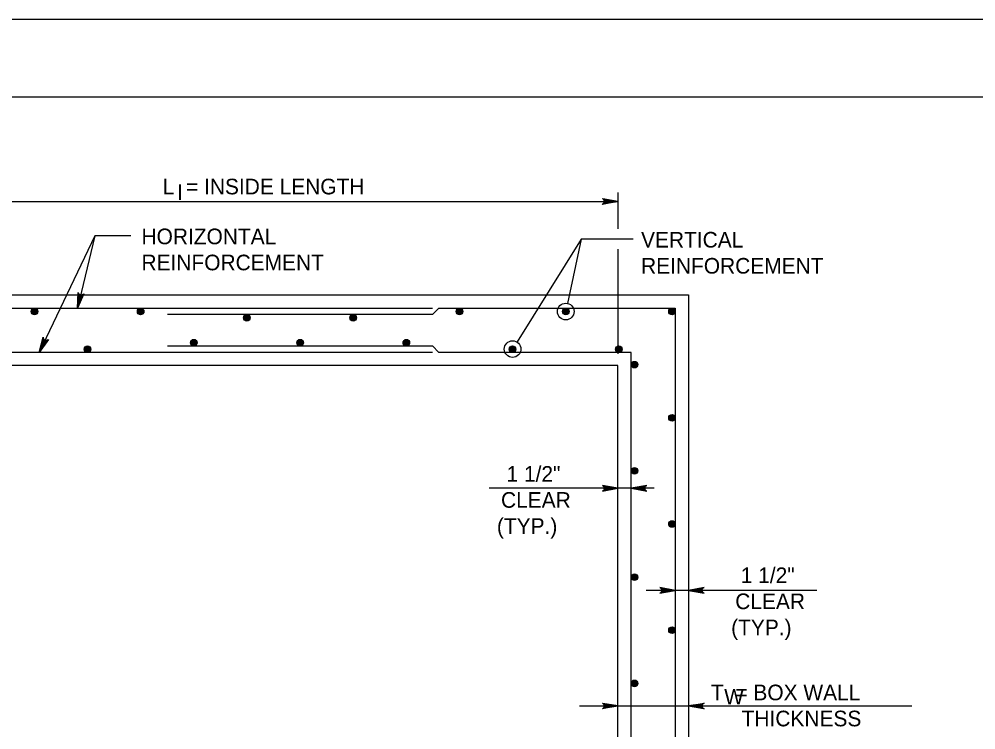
# Model space of a CAD drawing. Extents: x -6420 to 49575, y -4552 to 11624.
# Drawn here: x 3139 to 3741, y 3381 to 3829 of the extents above; entities that cross this region are included whole.
import ezdxf

# ---------------------------------------------------------------- set-up
doc = ezdxf.new("R2010")
doc.units = 0
doc.layers.add('1', color=7, linetype='Continuous')
doc.layers.add('PLT-BNDY', color=7, linetype='Continuous')

msp = doc.modelspace()

# ---------------------------------------------------------------- linework, layer by layer
at = {"layer": '1'}
for p, q in [((3516, 3719.59), (3516, 3696.6)), ((3115.99, 3713.89), (3516, 3713.89)), ((3186.81, 3692.29), (3151.76, 3618.89)), ((3186.81, 3692.29), (3175.85, 3646.67)), ((3209.46, 3692.29), (3186.81, 3692.29)), ((3492.81, 3690.2), (3452.5, 3625.43)), ((3492.81, 3690.2), (3484.25, 3649.72)), ((3525.48, 3690.2), (3492.81, 3690.2)), ((3516, 3683.79), (3516, 3617.96)), ((3079.87, 3646.67), (3399.33, 3646.67)), ((3399.33, 3642.67), (3232.66, 3642.67)), ((3399.33, 3642.67), (3403.33, 3646.67)), ((3403.33, 3646.67), (3552.11, 3646.67)), ((3483.16, 3644.58), (3483.16, 3644.58)), ((3552.11, 3646.67), (3552.11, 3174.43)), ((3399.33, 3618.89), (3107.66, 3618.89)), ((3232.66, 3622.89), (3399.33, 3622.89)), ((3399.33, 3622.89), (3403.33, 3618.89)), ((3524.33, 3618.89), (3403.33, 3618.89)), ((3449.73, 3620.97), (3449.73, 3620.97)), ((3524.33, 3202.21), (3524.33, 3618.89)), ((3538.89, 3533.32), (3434.99, 3533.32)), ((3641.23, 3469.09), (3533.8, 3469.09)), ((3491.9, 3396.36), (3700.86, 3396.36))]:
    msp.add_line(p, q, dxfattribs=at)
for points in [[(4563.89, 1929.01), (4563.89, 3779.41), (1985.15, 3779.41), (1985.15, 1929.01), (4563.89, 1929.01), (4563.89, 2015.49), (3907.72, 2015.49), (3907.72, 2227.69), (4563.89, 2227.69), (4563.89, 2322.72), (3907.72, 2322.72), (3907.72, 1929.01), (4166.25, 1929.01), (4166.25, 2015.49), (4166.25, 1929.01), (4418.88, 1929.01), (4418.88, 2015.49), (4418.88, 1975.09), (4563.89, 1975.09)], [(3516, 3713.89), (3506.21, 3712.05), (3506.59, 3712.31), (3506.97, 3712.58), (3507.16, 3712.9), (3507.35, 3713.23), (3507.41, 3713.56), (3507.47, 3713.89), (3507.41, 3714.22), (3507.35, 3714.54), (3507.16, 3714.87), (3506.97, 3715.2), (3506.59, 3715.46), (3506.21, 3715.72), (3516, 3713.89), (3506.59, 3715.46), (3506.97, 3715.2), (3516, 3713.89), (3507.16, 3714.87), (3507.35, 3714.54), (3516, 3713.89), (3507.41, 3714.22), (3507.47, 3713.89), (3516, 3713.89), (3507.41, 3713.56), (3507.35, 3713.23), (3516, 3713.89), (3507.16, 3712.9), (3506.97, 3712.58), (3516, 3713.89), (3506.59, 3712.31)], [(3175.85, 3646.67), (3176.35, 3656.61), (3176.52, 3656.18), (3176.69, 3655.76), (3176.96, 3655.49), (3177.23, 3655.22), (3177.54, 3655.09), (3177.85, 3654.96), (3178.18, 3654.94), (3178.51, 3654.92), (3178.87, 3655.03), (3179.24, 3655.14), (3179.58, 3655.45), (3179.92, 3655.75), (3175.85, 3646.67), (3179.58, 3655.45), (3179.24, 3655.14), (3175.85, 3646.67), (3178.87, 3655.03), (3178.51, 3654.92), (3175.85, 3646.67), (3178.18, 3654.94), (3177.85, 3654.96), (3175.85, 3646.67), (3177.54, 3655.09), (3177.23, 3655.22), (3175.85, 3646.67), (3176.96, 3655.49), (3176.69, 3655.76), (3175.85, 3646.67), (3176.52, 3656.18)], [(3151.76, 3618.89), (3154.32, 3628.51), (3154.39, 3628.06), (3154.46, 3627.6), (3154.68, 3627.29), (3154.89, 3626.97), (3155.16, 3626.78), (3155.43, 3626.58), (3155.75, 3626.49), (3156.07, 3626.4), (3156.45, 3626.44), (3156.83, 3626.47), (3157.23, 3626.7), (3157.63, 3626.93), (3151.76, 3618.89), (3157.23, 3626.7), (3156.83, 3626.47), (3151.76, 3618.89), (3156.45, 3626.44), (3156.07, 3626.4), (3151.76, 3618.89), (3155.75, 3626.49), (3155.43, 3626.58), (3151.76, 3618.89), (3155.16, 3626.78), (3154.89, 3626.97), (3151.76, 3618.89), (3154.68, 3627.29), (3154.46, 3627.6), (3151.76, 3618.89), (3154.39, 3628.06)], [(3516, 3533.32), (3506.21, 3535.15), (3506.59, 3534.89), (3506.97, 3534.63), (3507.16, 3534.3), (3507.35, 3533.97), (3507.41, 3533.64), (3507.47, 3533.32), (3507.41, 3532.99), (3507.35, 3532.66), (3507.16, 3532.33), (3506.97, 3532), (3506.59, 3531.74), (3506.21, 3531.48), (3516, 3533.32), (3506.59, 3531.74), (3506.97, 3532), (3516, 3533.32), (3507.16, 3532.33), (3507.35, 3532.66), (3516, 3533.32), (3507.41, 3532.99), (3507.47, 3533.32), (3516, 3533.32), (3507.41, 3533.64), (3507.35, 3533.97), (3516, 3533.32), (3507.16, 3534.3), (3506.97, 3534.63), (3516, 3533.32), (3506.59, 3534.89)], [(3524.33, 3533.32), (3534.12, 3531.48), (3533.74, 3531.74), (3533.36, 3532), (3533.17, 3532.33), (3532.97, 3532.66), (3532.92, 3532.99), (3532.86, 3533.32), (3532.92, 3533.64), (3532.97, 3533.97), (3533.17, 3534.3), (3533.36, 3534.63), (3533.74, 3534.89), (3534.12, 3535.15), (3524.33, 3533.32), (3533.74, 3534.89), (3533.36, 3534.63), (3524.33, 3533.32), (3533.17, 3534.3), (3532.97, 3533.97), (3524.33, 3533.32), (3532.92, 3533.64), (3532.86, 3533.32), (3524.33, 3533.32), (3532.92, 3532.99), (3532.97, 3532.66), (3524.33, 3533.32), (3533.17, 3532.33), (3533.36, 3532), (3524.33, 3533.32), (3533.74, 3531.74)], [(3552.11, 3469.09), (3542.33, 3470.92), (3542.7, 3470.66), (3543.08, 3470.4), (3543.27, 3470.07), (3543.47, 3469.74), (3543.52, 3469.42), (3543.58, 3469.09), (3543.52, 3468.76), (3543.47, 3468.43), (3543.27, 3468.1), (3543.08, 3467.78), (3542.7, 3467.51), (3542.33, 3467.25), (3552.11, 3469.09), (3542.7, 3467.51), (3543.08, 3467.78), (3552.11, 3469.09), (3543.27, 3468.1), (3543.47, 3468.43), (3552.11, 3469.09), (3543.52, 3468.76), (3543.58, 3469.09), (3552.11, 3469.09), (3543.52, 3469.42), (3543.47, 3469.74), (3552.11, 3469.09), (3543.27, 3470.07), (3543.08, 3470.4), (3552.11, 3469.09), (3542.7, 3470.66)], [(3560.44, 3469.09), (3570.23, 3467.25), (3569.85, 3467.51), (3569.48, 3467.78), (3569.28, 3468.1), (3569.09, 3468.43), (3569.03, 3468.76), (3568.97, 3469.09), (3569.03, 3469.42), (3569.09, 3469.74), (3569.28, 3470.07), (3569.48, 3470.4), (3569.85, 3470.66), (3570.23, 3470.92), (3560.44, 3469.09), (3569.85, 3470.66), (3569.48, 3470.4), (3560.44, 3469.09), (3569.28, 3470.07), (3569.09, 3469.74), (3560.44, 3469.09), (3569.03, 3469.42), (3568.97, 3469.09), (3560.44, 3469.09), (3569.03, 3468.76), (3569.09, 3468.43), (3560.44, 3469.09), (3569.28, 3468.1), (3569.48, 3467.78), (3560.44, 3469.09), (3569.85, 3467.51)], [(3516, 3396.36), (3506.21, 3394.52), (3506.59, 3394.78), (3506.97, 3395.04), (3507.16, 3395.37), (3507.35, 3395.7), (3507.41, 3396.03), (3507.47, 3396.36), (3507.41, 3396.68), (3507.35, 3397.01), (3507.16, 3397.34), (3506.97, 3397.67), (3506.59, 3397.93), (3506.21, 3398.19), (3516, 3396.36), (3506.59, 3397.93), (3506.97, 3397.67), (3516, 3396.36), (3507.16, 3397.34), (3507.35, 3397.01), (3516, 3396.36), (3507.41, 3396.68), (3507.47, 3396.36), (3516, 3396.36), (3507.41, 3396.03), (3507.35, 3395.7), (3516, 3396.36), (3507.16, 3395.37), (3506.97, 3395.04), (3516, 3396.36), (3506.59, 3394.78)], [(3560.44, 3396.36), (3570.23, 3398.19), (3569.85, 3397.93), (3569.48, 3397.67), (3569.28, 3397.34), (3569.09, 3397.01), (3569.03, 3396.68), (3568.97, 3396.36), (3569.03, 3396.03), (3569.09, 3395.7), (3569.28, 3395.37), (3569.48, 3395.04), (3569.85, 3394.78), (3570.23, 3394.52), (3560.44, 3396.36), (3569.85, 3394.78), (3569.48, 3395.04), (3560.44, 3396.36), (3569.28, 3395.37), (3569.09, 3395.7), (3560.44, 3396.36), (3569.03, 3396.03), (3568.97, 3396.36), (3560.44, 3396.36), (3569.03, 3396.68), (3569.09, 3397.01), (3560.44, 3396.36), (3569.28, 3397.34), (3569.48, 3397.67), (3560.44, 3396.36), (3569.85, 3397.93)]]:
    msp.add_lwpolyline(points, dxfattribs=at)
for points in [[(3071.54, 3655), (3560.44, 3655), (3560.44, 3166.1), (3071.54, 3166.1)], [(3115.99, 3210.55), (3516, 3210.55), (3516, 3610.55), (3115.99, 3610.55)]]:
    msp.add_lwpolyline(points, close=True, dxfattribs=at)
for centre, radius in [((3483.16, 3644.58), 5.25), ((3148.83, 3644.58), 2.08), ((3148.83, 3644.58), 1.94), ((3148.83, 3644.58), 1.79), ((3148.83, 3644.58), 1.64), ((3148.83, 3644.58), 1.49), ((3148.83, 3644.58), 1.34), ((3148.83, 3644.58), 1.2), ((3148.83, 3644.58), 1.05), ((3148.83, 3644.58), 0.9), ((3148.83, 3644.58), 0.752), ((3148.83, 3644.58), 0.604), ((3148.83, 3644.58), 0.456), ((3148.83, 3644.58), 0.308), ((3148.83, 3644.58), 0.16), ((3215.69, 3644.58), 2.08), ((3215.69, 3644.58), 1.94), ((3215.69, 3644.58), 1.79), ((3215.69, 3644.58), 1.64), ((3215.69, 3644.58), 1.49), ((3215.69, 3644.58), 1.34), ((3215.69, 3644.58), 1.2), ((3215.69, 3644.58), 1.05), ((3215.69, 3644.58), 0.9), ((3215.69, 3644.58), 0.752), ((3215.69, 3644.58), 0.604), ((3215.69, 3644.58), 0.456), ((3215.69, 3644.58), 0.308), ((3215.69, 3644.58), 0.16), ((3282.56, 3640.58), 2.08), ((3282.56, 3640.58), 1.94), ((3282.56, 3640.58), 1.79), ((3282.56, 3640.58), 1.64), ((3282.56, 3640.58), 1.49), ((3349.43, 3640.58), 2.08), ((3349.43, 3640.58), 1.94), ((3349.43, 3640.58), 1.79), ((3349.43, 3640.58), 1.64), ((3349.43, 3640.58), 1.49), ((3416.29, 3644.58), 2.08), ((3416.29, 3644.58), 1.94), ((3416.29, 3644.58), 1.79), ((3416.29, 3644.58), 1.64), ((3416.29, 3644.58), 1.49), ((3416.29, 3644.58), 1.34), ((3416.29, 3644.58), 1.2), ((3416.29, 3644.58), 1.05), ((3416.29, 3644.58), 0.9), ((3416.29, 3644.58), 0.752), ((3416.29, 3644.58), 0.604), ((3416.29, 3644.58), 0.456), ((3416.29, 3644.58), 0.308), ((3416.29, 3644.58), 0.16), ((3483.16, 3644.58), 2.08), ((3483.16, 3644.58), 1.94), ((3483.16, 3644.58), 1.79), ((3483.16, 3644.58), 1.64), ((3483.16, 3644.58), 1.49), ((3483.16, 3644.58), 1.34), ((3483.16, 3644.58), 1.2), ((3483.16, 3644.58), 1.05), ((3483.16, 3644.58), 0.9), ((3483.16, 3644.58), 0.752), ((3483.16, 3644.58), 0.604), ((3483.16, 3644.58), 0.456), ((3483.16, 3644.58), 0.308), ((3483.16, 3644.58), 0.16), ((3550.02, 3644.58), 2.08), ((3550.02, 3644.58), 1.94), ((3550.02, 3644.58), 1.79), ((3550.02, 3644.58), 1.64), ((3550.02, 3644.58), 1.49), ((3550.02, 3644.58), 1.34), ((3550.02, 3644.58), 1.2), ((3550.02, 3644.58), 1.05), ((3550.02, 3644.58), 0.9), ((3550.02, 3644.58), 0.752), ((3550.02, 3644.58), 0.604), ((3550.02, 3644.58), 0.456), ((3550.02, 3644.58), 0.308), ((3550.02, 3644.58), 0.16), ((3282.56, 3640.58), 1.34), ((3282.56, 3640.58), 1.2), ((3282.56, 3640.58), 1.05), ((3282.56, 3640.58), 0.9), ((3282.56, 3640.58), 0.752), ((3282.56, 3640.58), 0.604), ((3282.56, 3640.58), 0.456), ((3282.56, 3640.58), 0.308), ((3282.56, 3640.58), 0.16), ((3349.43, 3640.58), 1.34), ((3349.43, 3640.58), 1.2), ((3349.43, 3640.58), 1.05), ((3349.43, 3640.58), 0.9), ((3349.43, 3640.58), 0.752), ((3349.43, 3640.58), 0.604), ((3349.43, 3640.58), 0.456), ((3349.43, 3640.58), 0.308), ((3349.43, 3640.58), 0.16), ((3249.13, 3624.97), 2.08), ((3249.13, 3624.97), 1.94), ((3249.13, 3624.97), 1.79), ((3249.13, 3624.97), 1.64), ((3249.13, 3624.97), 1.49), ((3249.13, 3624.97), 1.34), ((3249.13, 3624.97), 1.2), ((3249.13, 3624.97), 1.05), ((3249.13, 3624.97), 0.9), ((3249.13, 3624.97), 0.752), ((3249.13, 3624.97), 0.604), ((3249.13, 3624.97), 0.456), ((3249.13, 3624.97), 0.308), ((3249.13, 3624.97), 0.16), ((3316, 3624.97), 2.08), ((3316, 3624.97), 1.94), ((3316, 3624.97), 1.79), ((3316, 3624.97), 1.64), ((3316, 3624.97), 1.49), ((3316, 3624.97), 1.34), ((3316, 3624.97), 1.2), ((3316, 3624.97), 1.05), ((3316, 3624.97), 0.9), ((3316, 3624.97), 0.752), ((3316, 3624.97), 0.604), ((3316, 3624.97), 0.456), ((3316, 3624.97), 0.308), ((3316, 3624.97), 0.16), ((3382.86, 3624.97), 2.08), ((3382.86, 3624.97), 1.94), ((3382.86, 3624.97), 1.79), ((3382.86, 3624.97), 1.64), ((3382.86, 3624.97), 1.49), ((3382.86, 3624.97), 1.34), ((3382.86, 3624.97), 1.2), ((3382.86, 3624.97), 1.05), ((3382.86, 3624.97), 0.9), ((3382.86, 3624.97), 0.752), ((3382.86, 3624.97), 0.604), ((3382.86, 3624.97), 0.456), ((3382.86, 3624.97), 0.308), ((3382.86, 3624.97), 0.16), ((3449.73, 3620.97), 5.25), ((3182.26, 3620.97), 2.08), ((3182.26, 3620.97), 1.94), ((3182.26, 3620.97), 1.79), ((3182.26, 3620.97), 1.64), ((3182.26, 3620.97), 1.49), ((3182.26, 3620.97), 1.34), ((3182.26, 3620.97), 1.2), ((3182.26, 3620.97), 1.05), ((3182.26, 3620.97), 0.9), ((3182.26, 3620.97), 0.752), ((3182.26, 3620.97), 0.604), ((3182.26, 3620.97), 0.456), ((3182.26, 3620.97), 0.308), ((3182.26, 3620.97), 0.16), ((3449.73, 3620.97), 2.08), ((3449.73, 3620.97), 1.94), ((3449.73, 3620.97), 1.79), ((3449.73, 3620.97), 1.64), ((3449.73, 3620.97), 1.49), ((3449.73, 3620.97), 1.34), ((3449.73, 3620.97), 1.2), ((3449.73, 3620.97), 1.05), ((3449.73, 3620.97), 0.9), ((3449.73, 3620.97), 0.752), ((3449.73, 3620.97), 0.604), ((3449.73, 3620.97), 0.456), ((3449.73, 3620.97), 0.308), ((3449.73, 3620.97), 0.16), ((3516.59, 3620.97), 2.08), ((3516.59, 3620.97), 1.94), ((3516.59, 3620.97), 1.79), ((3516.59, 3620.97), 1.64), ((3516.59, 3620.97), 1.49), ((3516.59, 3620.97), 1.34), ((3516.59, 3620.97), 1.2), ((3516.59, 3620.97), 1.05), ((3516.59, 3620.97), 0.9), ((3516.59, 3620.97), 0.752), ((3516.59, 3620.97), 0.604), ((3516.59, 3620.97), 0.456), ((3516.59, 3620.97), 0.308), ((3516.59, 3620.97), 0.16), ((3526.42, 3611.15), 2.08), ((3526.42, 3611.15), 1.94), ((3526.42, 3611.15), 1.79), ((3526.42, 3611.15), 1.64), ((3526.42, 3611.15), 1.49), ((3526.42, 3611.15), 1.34), ((3526.42, 3611.15), 1.2), ((3526.42, 3611.15), 1.05), ((3526.42, 3611.15), 0.9), ((3526.42, 3611.15), 0.752), ((3526.42, 3611.15), 0.604), ((3526.42, 3611.15), 0.456), ((3526.42, 3611.15), 0.308), ((3526.42, 3611.15), 0.16), ((3550.02, 3577.71), 2.08), ((3550.02, 3577.71), 1.94), ((3550.02, 3577.71), 1.79), ((3550.02, 3577.71), 1.64), ((3550.02, 3577.71), 1.49), ((3550.02, 3577.71), 1.34), ((3550.02, 3577.71), 1.2), ((3550.02, 3577.71), 1.05), ((3550.02, 3577.71), 0.9), ((3550.02, 3577.71), 0.752), ((3550.02, 3577.71), 0.604), ((3550.02, 3577.71), 0.456), ((3550.02, 3577.71), 0.308), ((3550.02, 3577.71), 0.16), ((3526.42, 3544.29), 2.08), ((3526.42, 3544.29), 1.94), ((3526.42, 3544.29), 1.79), ((3526.42, 3544.29), 1.64), ((3526.42, 3544.29), 1.49), ((3526.42, 3544.29), 1.34), ((3526.42, 3544.29), 1.2), ((3526.42, 3544.29), 1.05), ((3526.42, 3544.29), 0.9), ((3526.42, 3544.29), 0.752), ((3526.42, 3544.29), 0.604), ((3526.42, 3544.29), 0.456), ((3526.42, 3544.29), 0.308), ((3526.42, 3544.29), 0.16), ((3550.02, 3510.85), 2.08), ((3550.02, 3510.85), 1.94), ((3550.02, 3510.85), 1.79), ((3550.02, 3510.85), 1.64), ((3550.02, 3510.85), 1.49), ((3550.02, 3510.85), 1.34), ((3550.02, 3510.85), 1.2), ((3550.02, 3510.85), 1.05), ((3550.02, 3510.85), 0.9), ((3550.02, 3510.85), 0.752), ((3550.02, 3510.85), 0.604), ((3550.02, 3510.85), 0.456), ((3550.02, 3510.85), 0.308), ((3550.02, 3510.85), 0.16), ((3526.42, 3477.42), 2.08), ((3526.42, 3477.42), 1.94), ((3526.42, 3477.42), 1.79), ((3526.42, 3477.42), 1.64), ((3526.42, 3477.42), 1.49), ((3526.42, 3477.42), 1.34), ((3526.42, 3477.42), 1.2), ((3526.42, 3477.42), 1.05), ((3526.42, 3477.42), 0.9), ((3526.42, 3477.42), 0.752), ((3526.42, 3477.42), 0.604), ((3526.42, 3477.42), 0.456), ((3526.42, 3477.42), 0.308), ((3526.42, 3477.42), 0.16), ((3550.02, 3443.98), 2.08), ((3550.02, 3443.98), 1.94), ((3550.02, 3443.98), 1.79), ((3550.02, 3443.98), 1.64), ((3550.02, 3443.98), 1.49), ((3550.02, 3443.98), 1.34), ((3550.02, 3443.98), 1.2), ((3550.02, 3443.98), 1.05), ((3550.02, 3443.98), 0.9), ((3550.02, 3443.98), 0.752), ((3550.02, 3443.98), 0.604), ((3550.02, 3443.98), 0.456), ((3550.02, 3443.98), 0.308), ((3550.02, 3443.98), 0.16), ((3526.42, 3410.55), 2.08), ((3526.42, 3410.55), 1.94), ((3526.42, 3410.55), 1.79), ((3526.42, 3410.55), 1.64), ((3526.42, 3410.55), 1.49), ((3526.42, 3410.55), 1.34), ((3526.42, 3410.55), 1.2), ((3526.42, 3410.55), 1.05), ((3526.42, 3410.55), 0.9), ((3526.42, 3410.55), 0.752), ((3526.42, 3410.55), 0.604), ((3526.42, 3410.55), 0.456), ((3526.42, 3410.55), 0.308), ((3526.42, 3410.55), 0.16)]:
    msp.add_circle(centre, radius, dxfattribs=at)
at = {"layer": 'PLT-BNDY'}
msp.add_lwpolyline([(1857.19, 3828.62), (4616.38, 3828.62), (4616.38, 1879.8), (1857.19, 1879.8)], close=True, dxfattribs=at)

# ---------------------------------------------------------------- texts
at = {"layer": '1'}
for s, height, p in [('L  = INSIDE LENGTH', 9.8425, (3229.6, 3718.33)), ('I', 9.84, (3238.69, 3714.71)), ('HORIZONTAL', 9.843, (3216.21, 3686.94)), ('VERTICAL', 9.843, (3530.55, 3684.85)), ('REINFORCEMENT', 9.8425, (3216.21, 3670.53)), ('REINFORCEMENT', 9.8425, (3530.55, 3668.45)), ('1 1/2"', 9.843, (3445.89, 3537.47)), ('CLEAR', 9.843, (3442.44, 3521.07)), ('(TYP.)', 9.843, (3439.85, 3504.66)), ('1 1/2"', 9.843, (3593.27, 3473.66)), ('CLEAR', 9.843, (3589.82, 3457.26)), ('(TYP.)', 9.843, (3587.23, 3440.85)), ('T  = BOX WALL', 9.8425, (3574.54, 3399.91)), ('W', 9.84, (3582.83, 3397.26)), ('THICKNESS', 9.843, (3593.84, 3383.51))]:
    msp.add_text(s, height=height, dxfattribs=at).set_placement(p)

doc.saveas('drawing.dxf')
